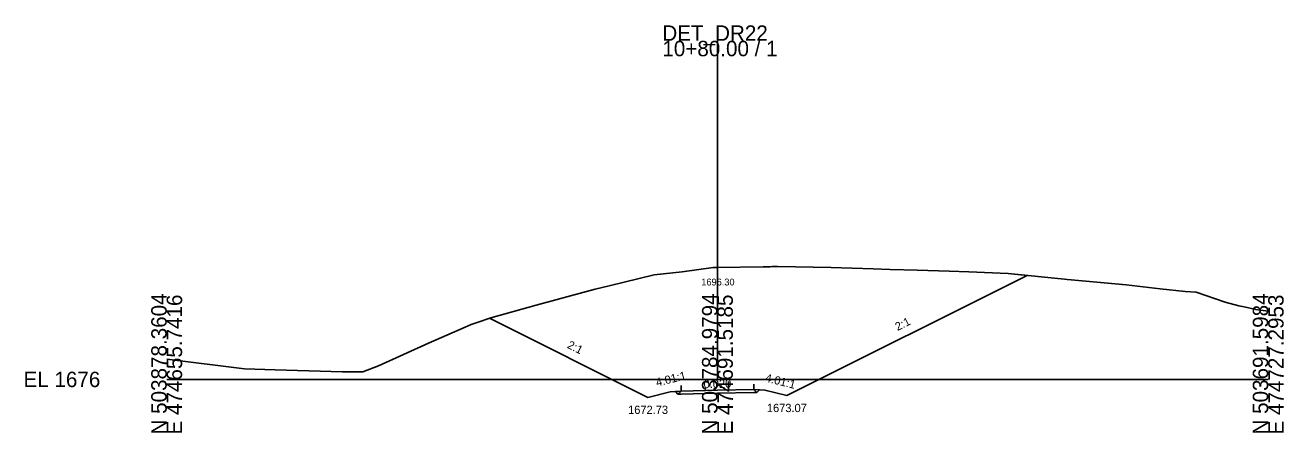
# Model space of a CAD drawing. Extents: x -26 to 1203, y -10 to 9633.
# Drawn here: x -25.7 to 202.8, y 1990.3 to 2064.3 of the extents above; entities that cross this region are included whole.
import ezdxf

# ---------------------------------------------------------------- set-up
doc = ezdxf.new("R2010")
doc.units = 0
for name, color, linetype in [('Exist Cross Section Cell', 7, 'Continuous'), ('Exist XS Center Line Elevation Label', 7, 'Continuous'), ('Exist XS Ground Line', 7, 'Continuous'), ('Prop XS Ditch Slope Text', 7, 'Continuous'), ('Prop XS Ditch Standard Text', 7, 'Continuous'), ('Prop XS Earthwork Shape', 7, 'Continuous'), ('Prop XS EOT Tick Mark', 7, 'Continuous'), ('Prop XS Finish Grade', 7, 'Continuous'), ('Prop XS Finish Grade Earthwork', 7, 'Continuous'), ('Prop XS Finish Grade Pavement', 7, 'Continuous'), ('Prop XS Pvmt Edge Slope', 7, 'Continuous'), ('Prop XS SE Text', 7, 'Continuous'), ('Prop XS Shoulder Borrow Shape', 7, 'Continuous'), ('Prop XS Side Slope Text', 7, 'Continuous'), ('Prop XS Subgrade Earthwork', 7, 'Continuous')]:
    doc.layers.add(name, color=color, linetype=linetype)

msp = doc.modelspace()

# ---------------------------------------------------------------- linework, layer by layer
at = {"layer": 'Exist Cross Section Cell'}
for p, q in [((100, 2000), (100, 2061.46)), ((0, 2000), (100, 2000)), ((100, 2000), (200, 2000))]:
    msp.add_line(p, q, dxfattribs=at)
at = {"layer": 'Exist XS Ground Line'}
msp.add_lwpolyline([(0, 2003.66), (14.11, 2001.9), (19.69, 2001.74), (31.91, 2001.35), (35.59, 2001.39), (38.47, 2002.46), (47.51, 2006.56), (54.21, 2009.46), (55.28, 2009.96), (56.38, 2010.34), (58.84, 2011.16), (67.09, 2013.45), (76.21, 2015.98), (77.8, 2016.4), (80.36, 2017.01), (88.51, 2018.97), (93.57, 2019.54), (99.22, 2020.29), (100, 2020.3), (108.32, 2020.45), (109.56, 2020.41), (109.93, 2020.47), (110.93, 2020.49), (120.64, 2020.34), (128.3, 2020.1), (131.35, 2019.94), (136.27, 2019.83), (142.06, 2019.65), (145.66, 2019.55), (152.77, 2019.21), (163.02, 2018.17), (163.48, 2018.12), (164.23, 2018.06), (174.2, 2017.18), (180.39, 2016.46), (184.91, 2015.97), (186.92, 2015.85), (192.18, 2014.04), (194.67, 2013.35), (195.62, 2013.15), (197.75, 2012.69), (200, 2012.37)], dxfattribs=at)
at = {"layer": 'Prop XS Earthwork Shape'}
msp.add_lwpolyline([(100, 1997.48), (93.39, 1997.35), (92.84, 1997.34), (92.37, 1997.81), (91.39, 1997.73), (87.38, 1996.73), (58.61, 2011.09), (58.84, 2011.16), (67.09, 2013.45), (76.21, 2015.98), (77.8, 2016.4), (80.36, 2017.01), (88.51, 2018.97), (93.57, 2019.54), (99.22, 2020.29), (100, 2020.3), (108.32, 2020.45), (109.56, 2020.41), (109.93, 2020.47), (110.93, 2020.49), (120.64, 2020.34), (128.3, 2020.1), (131.35, 2019.94), (136.27, 2019.83), (142.06, 2019.65), (145.66, 2019.55), (152.77, 2019.21), (156.26, 2018.85), (112.62, 1997.07), (108.61, 1998.07), (107.63, 1998.11), (107.14, 1997.62), (106.61, 1997.61)], close=True, dxfattribs=at)
at = {"layer": 'Prop XS EOT Tick Mark'}
for p, q in [((93.39, 1997.89), (93.39, 1998.89)), ((106.61, 1998.15), (106.61, 1999.15))]:
    msp.add_line(p, q, dxfattribs=at)
at = {"layer": 'Prop XS Finish Grade'}
for p, q in [((93.39, 1997.89), (92.37, 1997.81)), ((106.61, 1998.15), (107.63, 1998.11))]:
    msp.add_line(p, q, dxfattribs=at)
at = {"layer": 'Prop XS Finish Grade Earthwork'}
for p, q in [((112.62, 1997.07), (156.26, 2018.85)), ((87.38, 1996.73), (58.61, 2011.09)), ((91.39, 1997.73), (87.38, 1996.73)), ((92.37, 1997.81), (91.39, 1997.73)), ((107.63, 1998.11), (108.61, 1998.07)), ((108.61, 1998.07), (112.62, 1997.07))]:
    msp.add_line(p, q, dxfattribs=at)
at = {"layer": 'Prop XS Finish Grade Pavement'}
for p, q in [((93.39, 1997.89), (100, 1998.02)), ((100, 1998.02), (106.61, 1998.15))]:
    msp.add_line(p, q, dxfattribs=at)
at = {"layer": 'Prop XS Pvmt Edge Slope'}
for p, q in [((93.39, 1997.89), (92.84, 1997.34)), ((106.61, 1998.15), (107.14, 1997.62))]:
    msp.add_line(p, q, dxfattribs=at)
at = {"layer": 'Prop XS Shoulder Borrow Shape'}
for points in [[(93.39, 1997.89), (92.37, 1997.81), (92.84, 1997.34)], [(106.61, 1998.15), (107.63, 1998.11), (107.14, 1997.62)]]:
    msp.add_lwpolyline(points, close=True, dxfattribs=at)
at = {"layer": 'Prop XS Subgrade Earthwork'}
for p, q in [((92.84, 1997.34), (92.37, 1997.81)), ((100, 1997.48), (93.39, 1997.35)), ((106.61, 1997.61), (100, 1997.48)), ((106.61, 1997.61), (107.14, 1997.62)), ((107.14, 1997.62), (107.63, 1998.11)), ((93.39, 1997.35), (92.84, 1997.34))]:
    msp.add_line(p, q, dxfattribs=at)

# ---------------------------------------------------------------- texts
at = {"layer": 'Exist Cross Section Cell'}
for s, p in [('DET_DR22', (90, 2061.46)), ('10+80.00 / 1', (90, 2058.66)), ('EL 1676', (-26, 1998.6))]:
    msp.add_text(s, height=2.8, dxfattribs=at).set_placement(p)
for s, p in [('N 503878.3604', (0, 1990)), ('E 474655.7416', (2.8, 1990)), ('N 503784.9794', (100, 1990)), ('E 474691.5185', (102.8, 1990)), ('N 503691.5984', (200, 1990)), ('E 474727.2953', (202.8, 1990))]:
    msp.add_text(s, height=2.8, rotation=90, dxfattribs=at).set_placement(p)
at = {"layer": 'Exist XS Center Line Elevation Label'}
msp.add_text('1696.30', height=1.25, dxfattribs=at).set_placement((97.07, 2017.05))
at = {"layer": 'Prop XS Ditch Slope Text'}
for rotation, p in [(14.012, (89.02, 1998.69)), (345.988, (108.56, 1999.63))]:
    msp.add_text('4.01:1', height=1.5, rotation=rotation, dxfattribs=at).set_placement(p)
at = {"layer": 'Prop XS Ditch Standard Text'}
for s, p in [('1672.73', (83.78, 1993.73)), ('1673.07', (108.98, 1994.07))]:
    msp.add_text(s, height=1.5, dxfattribs=at).set_placement(p)
at = {"layer": 'Prop XS SE Text'}
msp.add_text('0.020', height=1.5, rotation=1.1458, dxfattribs=at).set_placement((97.5, 1998.4))
at = {"layer": 'Prop XS Side Slope Text'}
for rotation, p in [(26.5237, (132.71, 2008.78)), (333.4763, (72.6, 2005.78))]:
    msp.add_text('2:1', height=1.5, rotation=rotation, dxfattribs=at).set_placement(p)

doc.saveas('drawing.dxf')
